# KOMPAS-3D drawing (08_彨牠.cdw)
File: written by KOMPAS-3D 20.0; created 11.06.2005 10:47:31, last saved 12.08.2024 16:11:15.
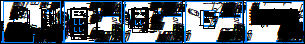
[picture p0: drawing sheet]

Sheets 1-5: A3, landscape

Document properties: Автор: ДВС; Организация: S&T; Разработал: Антошин; Проверил: Тарасов; Утвердил: Шмончев; Н. контр.: Силаков; Форматы листов документа: 5xA3

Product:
- Part/product: (unnamed)
  - Component: \\Helios\отдел_пко\Общая папка Компас\_Addons\Signatures\Signatures.lfr|Тарасов  | Полное имя файла: C:\Users\MAntoshin\AppData\Local\Temp\qlkzkl.frw; source file: C:\Program Files\ASCON\KOMPAS-3D V13\Libs\_Addons\Signatures\Signatures.lfr
  - Component: \\Helios\отдел_пко\Общая папка Компас\_Addons\Signatures\Signatures.lfr|Силаков  | Полное имя файла: C:\Users\MAntoshin\AppData\Local\Temp\eiczbt.frw; source file: C:\Program Files\ASCON\KOMPAS-3D V13\Libs\_Addons\Signatures\Signatures.lfr
  - Component: \\Helios\отдел_пко\Общая папка Компас\_Addons\Signatures\Signatures.lfr|Шмончев  | Полное имя файла: C:\Users\MAntoshin\AppData\Local\Temp\hsklda.frw; source file: C:\Program Files\ASCON\KOMPAS-3D V13\Libs\_Addons\Signatures\Signatures.lfr

Title block, sheet 1: designation: ВЛСТ 1277. 02. 000 С8; scale: 1:1; sheet number: 1; Количество листов документа: 3; organisation: АО ГК / "Системы и Технологии"; Форматы листов документа: A3; stored path: D:\User\Семёнов\Планы\СЭС\ПС№9 Подсобное хозяйство\ПС№9 Подсобное хозяйство.cdw; cell 302: Система учета электроэнергии (с организацией удаленного / сбора данных) потребителей; cell 303: Типовой проект ИСУЭ / многоквартирного дома с использованием / радиоканала (F2/868 МГц); cell 304: План расположения оборудования / и проводок; cell 320: Р
Title block, sheet 2: sheet number: 2; sheet number: 3; stored path: Z:\МРСК Северо-Запада Псковэнерго\Типовой проект\Рабочая документация\С8_005_План_многоквартирный_дом_PLC.cdw
Title block, sheet 3: stored path: \\fs1.s-tech.ru\depts\Отдел_ПКО\Проекты\ГУП СК Ставрополькоммунэлектро\2021\Типовой проект\02_Рабочая документация\С8_001_План_многоквартирный_дом_УСПД.cdw
Title block, sheet 4: sheet number: 4; stored path: \\s-tech\depts\Отдел_ПКО\Проекты\Типовые проекты МКД 2023\!Типовой проект\2_Типовой проект МКД_Радиоканал\08_План.cdw
Title block, sheet 5: sheet number: 5; designation, second copy: ВЛСТ 1277. 02. 000 С8-

Referenced files in \\Helios\отдел_пко\Общая папка Компас\_Addons\Signatures\: Signatures.lfr|Тарасов, Signatures.lfr, Signatures.lfr|Силаков, Signatures.lfr|Шмончев
Referenced files in C:\Program Files\ASCON\KOMPAS-3D V13\Libs\_Addons\Signatures\: Signatures.lfr
Referenced files: qlkzkl.frw, eiczbt.frw, hsklda.frw
Referenced files in C:\Program Files\ASCON\KOMPAS-3D v20\Sys\: Graphic.lcs
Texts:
  Тарасов
  Силаков
  Шмончев
  Лит-Масса-Масштаб
  Материал-Предприятие
  Z-начало формы
  Z-конец формы
  Форматированный
  Courier New
  Цитаты
  Адрес
  Список определений
  Термин
  Обычный
  heading 2
  Body Text
  heading 1
  Normal
  Без имени
  Centerline
  Outline
  Этажный щит (4 счетчика)
  Существующие кабельные каналы
  Таблица 1 - Перечень оборудования
  поз.
  Кол-во
  Счетчик электроэнергии
  DIN рейка
  Автоматический выключатель
  Разборные контактные
  соединения
  Шкаф УСПД
  GSM-антенна
  ВРУ №1
  План размещения проектируемого оборудования в помещении электрощитовой
  Этажный щит (2 счетчика)
  Таблица 2 - Перечень оборудования
  Коробка разветвительная RS-485
  Счетчик
  Этаж 1
  Этаж 2
  Этаж 3
  Этаж N
  Подъезд 1
  Подъезд 2
  Подъезд K
  Схема расположения выносных антенн RF-868 МГц на фасаде МКД
  Щит индивидуальный в квартире (на 1 счетчик)
  Таблица 3 - Перечень оборудования
  1. Размеры со знаком "*" указаны для информации.
  1. Вновь устанавливаемое оборудование изображается утолщенной линией.
  2. Размеры указаны в метрах.
  3. При прокладке кабелей соблюдать требования РД 34.20.116-93.
  4. Способ прокладки интерфейсного кабеля уточнить при проведении СМР.
  5. При монтаже оборудования руководствоваться соответствующими разделами эксплуатационной документации
  оборудования.
  6. Итоговый вариант размещения оборудования определяется на этапе адаптации типового проекта к конкретному
  объекту.
  7. Габаритные размеры щитов этажных должны соответствовать габаритным размерым приборов учета т.е. при
  установке счетчиков ЭЭ дверца щитов должна легко закрываться, не должно возникать помех и сложностей с
  дальнейшим обслуживанием оборудования, смотровые окна щитов должны позволять абонентам выполнять просмотр
  данных со счетчиков и т.д.
  8. В соответствии с п.7 на этапе адаптации типового проекта к конкретному объекту выбрать исполнение (W или W2)
  однофазного счетчика электроэнергии КВАНТ ST 1000-9. Габаритные, присоеднительные и установочные размеры
  указанных исполнений приведены на Чертеже установки технических средств ВЛСТ 1277.02.000 СА.
  1. Антенна RF-868 МГц для Link ST200 должна располагаться не ближе 1.5 метра от стены дома
  (рекомендуется на плоскую поверхность крыши подъезда или иной пристройки). Антенна показана условно.
  2. Штриховкой показана область на фасаде МКД для установки выносных антенн RF-868 МГц
  абонентских счетчиков. Устанавливать на 2 этаже и каждые +5 по этажам (7, 12, 17 и т.д.) в одной
  горизонтальной плоскости.
  3. При выборе мест установок выносных антенн RF-868 МГц на фасад МКД обеспечить  условие
  беспрепятственного прохождения сигнала между антеннами т.е. между антеннами должны отсутствовать
  преграды в виде стен, балконов и т.д.
  4. В зависимости от системы электроснабжения и типа МКД количество подъездов (K) и этажей (N)
  может изменяться.
  Этаж 7
  Сплошная тонкая с изломами
  ACAD_ISO04W100_RGB_0_0_0_SC_1_THICK_0.15
  СONTINUOUS_RGB_0_0_0_THICK_0.2
  СONTINUOUS_RGB_0_0_0_THICK_0.15
  ACAD_ISO02W100_RGB_0_0_0_SC_1_THICK_0.2
  Стили документа
  ANSI37
  План расположения
  оборудования и проводок
  Разраб.
  Н.контр.
  ПС "Сокольники" №76
  Антошин
  03 Рабочие чертежи основного комплекта. ГОСТ Р 21.1101-2009 Ф3
  Чертеж строит. Посл. листы.  ГОСТ Р 21.1101-2009 Ф6.
Dimensions and other numbers on the sheet: 35; 2; 3с5; 0,54; 0,065; 0,14; 0,105; 0,91; 1; 3; 0,8; 0,3; 1,2; 0,6; 0,29*; 0,4*; 7; 1:1; 04.23; 5; 4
